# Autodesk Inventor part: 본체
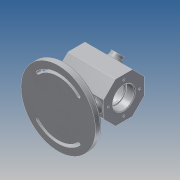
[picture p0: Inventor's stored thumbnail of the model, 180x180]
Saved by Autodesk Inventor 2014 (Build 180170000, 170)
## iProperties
Created: 2017-06
Part Number: 본체
Material: 알루미늄 6061
Document SubType Name: Modeling
Designer: 부인급구
Density: 2.71 g/cm^3
Appearance: 알루미늄 - 평지
Mass: 562.525 g
Surface Area: 565.555 cm^2
Volume: 207.574 cm^3
Author: 부인급구
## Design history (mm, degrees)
sketch "스케치1"
  geometry: C1 r 55 at (0, 0); 1 further point
  constraints: 1 centre point, 1 coincident
  dimensions: "d0" = 110 diameter of C1
extrude "돌출1" new body sketch "스케치1" distance "d1" = 10; taper "d2" = 0 deg
sketch "스케치2"
  geometry: L1 (0, 0)-(0, 48); L2 (30.406, -30.406)-(-33.941, 33.941); L3 (-30.406, -30.406)-(33.941, 33.941); C1 r 55 at (0, 0) reference; A1 r 5 centre (-30.406, 30.406) between (-26.87, 26.87) and (-33.73, 26.67); A2 r 5 centre (30.406, 30.406) between (26.87, 26.87) and (33.73, 26.67); A3 r 5 centre (30.406, -30.406) between (26.87, -26.87) and (33.73, -26.67); A4 r 5 centre (-30.406, -30.406) between (-26.87, -26.87) and (-33.73, -26.67); A5 r 38 centre (0, 0) between (-26.87, -26.87) and (26.87, -26.87); A6 r 38 centre (0, 0) between (26.87, 26.87) and (-26.87, 26.87); A7 r 43 centre (0, 0) between (-33.73, -26.67) and (33.73, -26.67); A8 r 43 centre (0, 0) between (33.73, 26.67) and (-33.73, 26.67); A9 r 48 centre (0, 0) between (33.941, 33.941) and (-33.941, 33.941); A10 r 48 centre (0, 0) between (-33.941, -33.941) and (33.941, -33.941)
  constraints: 30 point on circle, 10 centre point, 6 end point, 5 coincident, 4 point on line, 3 vertical alignment, 1 vertical
  dimensions: "d6" = 45 deg angle of L1 L2; "d7" = 90 deg angle of L3 L2; "d8" = 5 radius of A1; "d11" = 5 radius of A2; "d12" = 5 radius of A3; "d14" = 5 radius of A4; "d15" = 30.40559 horizontal distance of C1.centre A1.centre; "d16" = 3.53553 horizontal distance of A1.centre A1.start
extrude "돌출2" cut sketch "스케치2" distance "d17" = 3; taper "d18" = 0 deg
sketch "스케치3"
  geometry: A1 r 5 centre (-30.406, 30.406) between (-33.941, 33.941) and (-26.87, 26.87) reference; A2 r 38 centre (0, 0) between (26.87, 26.87) and (-26.87, 26.87) reference; A3 r 5 centre (30.406, 30.406) between (26.87, 26.87) and (33.941, 33.941) reference; A4 r 48 centre (0, 0) between (33.941, 33.941) and (-33.941, 33.941) reference; A5 r 5 centre (30.406, -30.406) between (33.941, -33.941) and (26.87, -26.87) reference; A6 r 38 centre (0, 0) between (-26.87, -26.87) and (26.87, -26.87) reference; A7 r 5 centre (-30.406, -30.406) between (-26.87, -26.87) and (-33.941, -33.941) reference; A8 r 48 centre (0, 0) between (-33.941, -33.941) and (33.941, -33.941) reference; A9 r 2 centre (-30.406, 30.406) between (-31.82, 31.82) and (-28.991, 28.991); A10 r 41 centre (0, 0) between (28.991, 28.991) and (-28.991, 28.991); A11 r 2 centre (30.406, 30.406) between (28.991, 28.991) and (31.82, 31.82); A12 r 45 centre (0, 0) between (31.82, 31.82) and (-31.82, 31.82); A13 r 2 centre (30.406, -30.406) between (31.82, -31.82) and (28.991, -28.991); A14 r 45 centre (0, 0) between (-31.82, -31.82) and (31.82, -31.82); A15 r 2 centre (-30.406, -30.406) between (-28.991, -28.991) and (-31.82, -31.82); A16 r 41 centre (0, 0) between (-28.991, -28.991) and (28.991, -28.991)
  constraints: 16 point on circle, 8 centre point, 6 other
  dimensions: "d19" = 2 radius of A15; "d20" = 2 radius of A9
extrude "돌출3" cut sketch "스케치3" stored distance "d21" = 3; taper "d22" = 0 deg
sketch "스케치4" dims "d23" = 60
  geometry: L1 (92, -12.426)-(74.426, -30); L2 (74.426, -30)-(49.574, -30); L3 (49.574, -30)-(32, -12.426); L4 (32, -12.426)-(32, 12.426); L5 (32, 12.426)-(49.574, 30); L6 (49.574, 30)-(74.426, 30); L7 (74.426, 30)-(92, 12.426); L8 (92, 12.426)-(92, -12.426); L9 (0, 55)-(0, -55) reference; 5 further points
  constraints: 16 end point, 3 horizontal alignment, 2 midpoint, 1 coincident, 19 other
  dimensions: "d24" = 62 distance from line of L9 point (62, 0)
extrude "돌출4" join sketch "스케치4" stored distance "d25" = 70; taper "d26" = 0 deg
sketch "스케치5"
  geometry: L1 (-24, 5)-(24, 5); L2 (24, 5)-(24, -5); L3 (24, -5)-(-24, -5); L4 (-24, -5)-(-24, 5); L5 (24, -5)-(-24, 5); C1 r 5 at (-24, 0); C2 r 5 at (24, 0); A1 r 38 centre (0, 0) between (-26.87, -26.87) and (26.87, -26.87) reference; 1 further point
  constraints: 10 end point, 3 midpoint, 2 centre point, 2 parallel, 1 coincident, 1 horizontal, 1 perpendicular
  dimensions: "d27" = 48 distance of L1.start L1.end; "d28" = 10 distance of L3.end L1.start; "d29" = 5 radius of C1; "d30" = 5 radius of C2
extrude "돌출5" join sketch "스케치5" stored distance "d31" = 70; taper "d32" = 0 deg
sketch "스케치6"
  geometry: L1 (0, 0)-(0, 24.853) reference; L2 (70, 42.426)-(0, 42.426) reference; 2 further points
  constraints: 1 other
  dimensions: "d33" = 35 distance from line of L1 point (35, 12.426); "d34" = 30 distance from line of L2 point (35, 12.426)
feature "엠보싱1" sketch "스케치6" dims "d6" = 45 deg, "d7" = 90 deg, "d8" = 5, "d11" = 5, "d12" = 5, "d14" = 5, "d15" = 30.40559, "d16" = 3.53553, "d35" = 0.5, "d36" = 0
sketch "스케치7"
  geometry: L1 (74.426, -30)-(92, -12.426) reference; L2 (92, -12.426)-(92, 12.426) reference; L3 (92, 12.426)-(74.426, 30) reference; L4 (74.426, 30)-(49.574, 30) reference; L5 (49.574, 30)-(32, 12.426) reference; L6 (32, 12.426)-(32, -12.426) reference; L7 (32, -12.426)-(49.574, -30) reference; L8 (49.574, -30)-(74.426, -30) reference; L9 (62, 50)-(62, -50); L10 (0, 55)-(0, -55) reference; L11 (62, 0)-(83.213, 21.213); 2 further points
  constraints: 4 end point, 3 midpoint, 1 horizontal alignment, 1 perpendicular
  dimensions: "d37" = 62 distance between parallel lines of L10 L9; "d38" = 45 deg angle of L9 L11
  node "투영된 루프2"
node "작업 평면1"
sketch "스케치8"
  geometry: C1 r 8 at (0, 0); 2 further points
  constraints: 1 centre point, 1 coincident
  dimensions: "d39" = 16 diameter of C1
extrude "돌출6" join sketch "스케치8" distance "d40" = 7; taper "d41" = 0 deg
sketch "스케치9"
  geometry: L1 (-55, 0)-(55, 0) reference; C1 r 16 at (0, 62); 2 further points
  constraints: 1 centre point, 1 midpoint, 1 vertical alignment
  dimensions: "d42" = 32 diameter of C1; "d43" = 62 distance from line of L1 C1.centre
extrude "돌출7" cut sketch "스케치9" distance "d44" = 12; taper "d45" = 0 deg
sketch "스케치10"
  geometry: C1 r 16 at (0, 0) reference; C2 r 14 at (0, 0); 1 further point
  constraints: 1 centre point, 1 coincident
  dimensions: "d46" = 28 diameter of C2
extrude "돌출8" cut sketch "스케치10" distance "d47" = 3; taper "d48" = 0 deg
sketch "스케치11"
  geometry: C1 r 14 at (0, 0) reference; C2 r 25 at (0, 0); 1 further point
  constraints: 1 centre point, 1 coincident
  dimensions: "d49" = 50 diameter of C2
extrude "돌출9" cut sketch "스케치11" distance "d50" = 40; taper "d51" = 0 deg
sketch "스케치12"
  geometry: C1 r 25 at (0, 0) reference; C2 r 14 at (0, 0); 1 further point
  constraints: 1 centre point, 1 coincident
  dimensions: "d52" = 28 diameter of C2
extrude "돌출10" cut sketch "스케치12" distance "d53" = 3; taper "d54" = 0 deg
sketch "스케치13"
  geometry: C1 r 14 at (0, 0) reference; C2 r 16 at (0, 0); 1 further point
  constraints: 1 centre point, 1 coincident
  dimensions: "d55" = 32 diameter of C2
extrude "돌출11" cut sketch "스케치13" distance "d56" = 12; taper "d57" = 0 deg
sketch "스케치14"
  geometry: C1 r 8 at (0, 0) reference; C2 r 4 at (0, 0); 1 further point
  constraints: 1 centre point, 1 coincident
  dimensions: "d58" = 8 diameter of C2
extrude "돌출12" cut sketch "스케치14" stored distance "d59" = 12; taper "d60" = 0 deg
sketch "스케치15" dims "d61" = 46
  geometry: L1 (12.426, 92)-(-12.426, 92) reference; L2 (0, 62)-(0, 85); C1 r 16 at (0, 62) reference; 2 further points
  constraints: 2 coincident, 2 end point, 1 perpendicular, 1 vertical alignment, 2 other
hole "구멍1" sketch "스케치15" at (0, 85) diameter "d62" = 3.242; stored, may be unused: countersink angle "d66" = 90 deg, drill point angle "d68" = 118 deg; dims "d63" = 8, "d64" = 4, "d65" = 2, "d67" = 10
fillet "모깎기1" dims "d72" = 0.3
fillet "모깎기2" dims "d73" = 1
fillet "모깎기3" dims "d74" = 3
fillet "모깎기4" dims "d75" = 5
chamfer "모따기1" distance "d76" = 1; stored, may be unused: second distance "d77" = 2, angle "d78" = 45 deg
node "솔리드1"
pattern_circular "원형 패턴1" dims angle "d70" = 360 deg
mirror "대칭1"
node "투영된 루프1"
other parameters: "d3" = 96, "d4" = 76, "d5" = 86
